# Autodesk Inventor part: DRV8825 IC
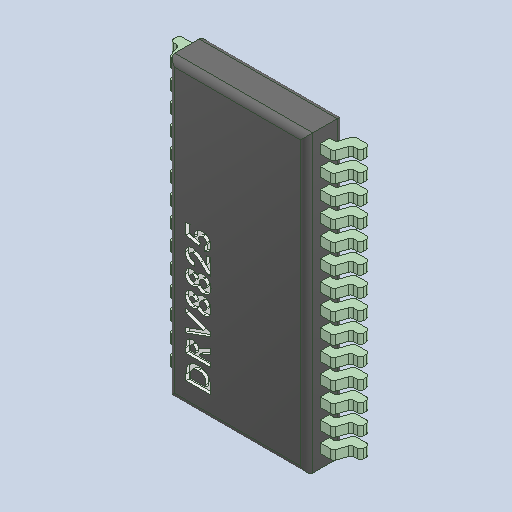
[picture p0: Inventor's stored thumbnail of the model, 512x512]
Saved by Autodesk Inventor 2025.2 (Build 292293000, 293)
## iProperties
Created: 2025-04
Part Number: DRV8825 IC
Material: Generic
Description: PART--DESC
Document SubType Name: Modeling
Designer: BennF
Density: 1 g/cm^3
Appearance: Default
Author: BennF
Revision Number: NONE
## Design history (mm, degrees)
feature "Solid1"
body "Solid2"
